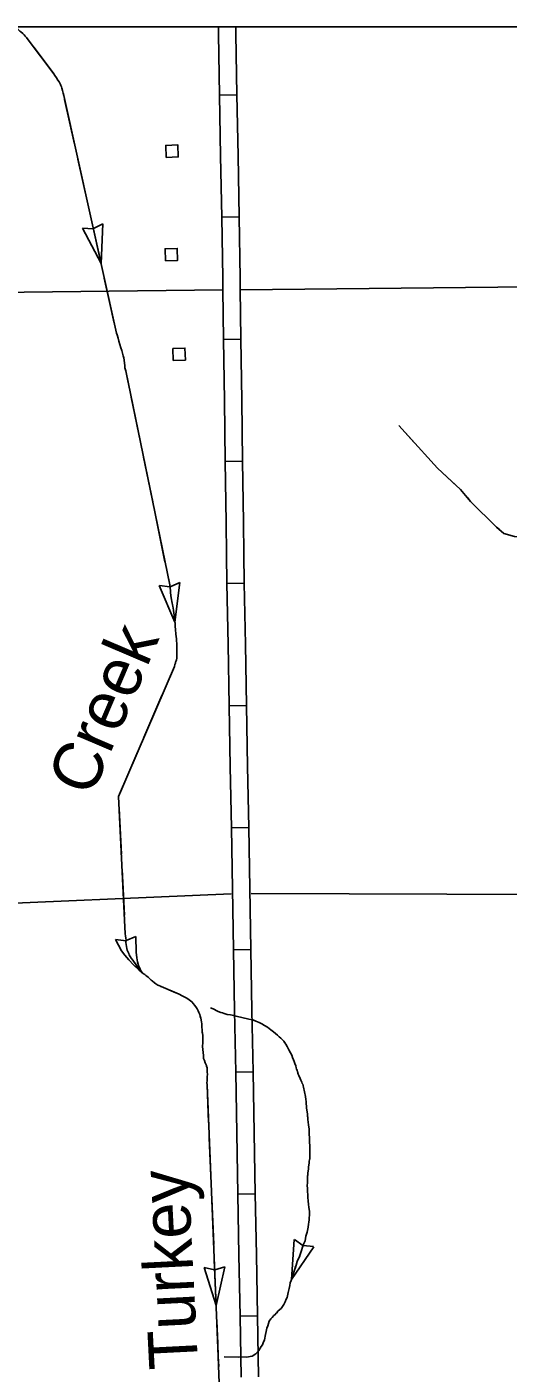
# Model space of a CAD drawing. Extents: x 1084508 to 1142749, y 1057638 to 1093403.
# Drawn here: x 1095928 to 1097232, y 1089750 to 1093403 of the extents above; entities that cross this region are included whole.
import ezdxf

# ---------------------------------------------------------------- set-up
doc = ezdxf.new("R2010")
doc.units = 0
for name, color, linetype in [('DSN_DRFT_Named-Boundary', 7, 'Continuous'), ('Level 31', 7, 'Continuous'), ('Level 35', 7, 'Continuous'), ('Level 43', 7, 'Continuous'), ('Level 5', 7, 'Continuous'), ('Level 56', 7, 'Continuous')]:
    doc.layers.add(name, color=color, linetype=linetype)

msp = doc.modelspace()

# ---------------------------------------------------------------- linework, layer by layer
at = {"layer": 'DSN_DRFT_Named-Boundary'}
msp.add_lwpolyline([(1084507.9, 1057640), (1142749.2, 1057640), (1142749.2, 1093403.4), (1084507.9, 1093403.4)], close=True, dxfattribs=at)
at = {"layer": 'Level 31'}
for p, q in [((1096447, 1093403.4), (1096447.3, 1093383.9)), ((1096494.1, 1093403.4), (1096494.4, 1093384.7)), ((1096497.2, 1093219), (1096450.1, 1093218.2)), ((1096455.7, 1092886.8), (1096502.8, 1092887.6)), ((1096460.8, 1092555.4), (1096507.9, 1092556.1)), ((1096512.3, 1092224.6), (1096465.2, 1092224)), ((1096470, 1091892.5), (1096517.1, 1091893.3)), ((1096523, 1091561.9), (1096475.9, 1091561.1)), ((1096481.9, 1091229.7), (1096528.9, 1091230.5)), ((1096534.9, 1090899.1), (1096487.8, 1090898.2)), ((1096540.8, 1090567.7), (1096493.7, 1090566.8)), ((1096499.6, 1090235.4), (1096546.7, 1090236.3)), ((1096505.6, 1089904), (1096552.6, 1089904.9))]:
    msp.add_line(p, q, dxfattribs=at)
for points in [[(1096447.3, 1093383.9), (1096450.1, 1093218.2)], [(1096494.4, 1093384.7), (1096497.2, 1093219)], [(1096450.1, 1093218.2), (1096452.9, 1093052.5)], [(1096500, 1093053.3), (1096497.2, 1093219)], [(1096452.9, 1093052.5), (1096455.7, 1092886.8)], [(1096502.8, 1092887.6), (1096500, 1093053.3)], [(1096455.7, 1092886.8), (1096458.5, 1092721.1)], [(1096502.8, 1092887.6), (1096505.6, 1092721.9)], [(1096458.5, 1092721.1), (1096459, 1092691.1), (1096460.8, 1092555.4)], [(1096505.6, 1092721.9), (1096506.1, 1092691.8), (1096507.9, 1092556.1)], [(1096463, 1092389.7), (1096460.8, 1092555.4)], [(1096507.9, 1092556.1), (1096510.1, 1092390.3)], [(1096465.2, 1092224), (1096463, 1092389.7)], [(1096510.1, 1092390.3), (1096512.3, 1092224.6)], [(1096465.2, 1092224), (1096467.4, 1092058.3)], [(1096512.3, 1092224.6), (1096514.5, 1092058.9)], [(1096467.4, 1092058.3), (1096468.6, 1091971.3), (1096470, 1091892.5)], [(1096514.5, 1092058.9), (1096515.7, 1091972), (1096517.1, 1091893.3)], [(1096473, 1091726.8), (1096470, 1091892.5)], [(1096517.1, 1091893.3), (1096520, 1091727.6)], [(1096475.9, 1091561.1), (1096473, 1091726.8)], [(1096520, 1091727.6), (1096523, 1091561.9)], [(1096475.9, 1091561.1), (1096478.9, 1091395.4)], [(1096523, 1091561.9), (1096526, 1091396.2)], [(1096478.9, 1091395.4), (1096481.9, 1091229.7)], [(1096526, 1091396.2), (1096528.9, 1091230.5)], [(1096484.8, 1091064), (1096481.9, 1091229.7)], [(1096528.9, 1091230.5), (1096531.9, 1091064.8)], [(1096487.8, 1090898.2), (1096484.8, 1091064)], [(1096531.9, 1091064.8), (1096534.9, 1090899.1)], [(1096487.8, 1090898.2), (1096490.7, 1090732.5)], [(1096534.9, 1090899.1), (1096537.8, 1090733.4)], [(1096490.7, 1090732.5), (1096493.7, 1090566.8)], [(1096537.8, 1090733.4), (1096540.8, 1090567.7)], [(1096493.7, 1090566.8), (1096496.7, 1090401.1)], [(1096543.7, 1090402), (1096540.8, 1090567.7)], [(1096496.7, 1090401.1), (1096499.6, 1090235.4)], [(1096546.7, 1090236.3), (1096543.7, 1090402)], [(1096499.6, 1090235.4), (1096502.6, 1090069.7)], [(1096546.7, 1090236.3), (1096549.7, 1090070.6)], [(1096502.6, 1090069.7), (1096505.6, 1089904)], [(1096549.7, 1090070.6), (1096552.6, 1089904.9)], [(1096508.5, 1089738.3), (1096505.6, 1089904)], [(1096552.6, 1089904.9), (1096555.6, 1089739.2)]]:
    msp.add_lwpolyline(points, dxfattribs=at)
at = {"layer": 'Level 43'}
for p, q in [((1096133.1, 1092869.1), (1096107.7, 1092855.9)), ((1096128.4, 1092761.5), (1096133.1, 1092869.1)), ((1096128.4, 1092761.5), (1096078.6, 1092857.1)), ((1096078.6, 1092857.1), (1096107.3, 1092855.8)), ((1096328.9, 1091788), (1096286.3, 1091887.3)), ((1096286.8, 1091887.4), (1096315.3, 1091883.9)), ((1096342, 1091895.1), (1096315.6, 1091883.9)), ((1096328.9, 1091788.2), (1096342.4, 1091895.3)), ((1096222.9, 1090934.6), (1096196.6, 1090923.4)), ((1096167.7, 1090926.7), (1096196.2, 1090923.3)), ((1096644.9, 1090004), (1096705.3, 1090092.7)), ((1096645.1, 1090004), (1096652.7, 1090112.1)), ((1096652.8, 1090112.3), (1096676.2, 1090095.7)), ((1096705.1, 1090092.9), (1096676.5, 1090095.6)), ((1096440.8, 1089933.2), (1096408.6, 1090036)), ((1096408.6, 1090036), (1096436.6, 1090029.7)), ((1096464.4, 1090038.3), (1096437, 1090029.7)), ((1096440.8, 1089933.2), (1096464.4, 1090038.3))]:
    msp.add_line(p, q, dxfattribs=at)
for points in [[(1095897.6, 1093403.4), (1095899.7, 1093401), (1095902.3, 1093398.3), (1095908.3, 1093392), (1095910.8, 1093390.1), (1095916, 1093385.8), (1095919.7, 1093381.6), (1095923, 1093378.2), (1095926.1, 1093374.7), (1095928.5, 1093371.8), (1096000.1, 1093275.6), (1096002.8, 1093271.3), (1096007.4, 1093265.2), (1096011.4, 1093259), (1096014.7, 1093254.7), (1096018.1, 1093247)], [(1095946.7, 1093347.4), (1096000.1, 1093275.6), (1096002.8, 1093271.3), (1096007.4, 1093265.2), (1096011.4, 1093259), (1096014.7, 1093254.7), (1096018.1, 1093247), (1096018.5, 1093246.2)], [(1096018.1, 1093247), (1096019.4, 1093244.4), (1096020.9, 1093241.1), (1096022.1, 1093236.8), (1096023.8, 1093231.1), (1096025.6, 1093223.9), (1096027.5, 1093216.8), (1096170.4, 1092572), (1096171.8, 1092567.6), (1096174.7, 1092558.9), (1096176.8, 1092550.8), (1096179.7, 1092541.5), (1096182.2, 1092532.8), (1096184.7, 1092524.7), (1096188.7, 1092510.9), (1096189.9, 1092505.3), (1096191.4, 1092499.1), (1096192.3, 1092490.9), (1096193.2, 1092484.7), (1096193.4, 1092478.4), (1096195.6, 1092470.3), (1096314.7, 1091888.8), (1096315.1, 1091886.2), (1096315.6, 1091881.6), (1096316.6, 1091872.3), (1096317.1, 1091868.6), (1096318, 1091860.1), (1096319, 1091854.2), (1096321.5, 1091839.4), (1096322.4, 1091836.2), (1096323.2, 1091829.9), (1096324, 1091826.5), (1096324.9, 1091819.3), (1096325.7, 1091813), (1096326.6, 1091806.8), (1096327, 1091802.1), (1096328.4, 1091791.1), (1096329.2, 1091783.6), (1096329.9, 1091777.3), (1096329.9, 1091774.8), (1096330.2, 1091769.1), (1096330.7, 1091764.1), (1096331.1, 1091759.2), (1096331.3, 1091755.3), (1096332.2, 1091749), (1096332.7, 1091743.4), (1096333.3, 1091738.3), (1096333.5, 1091735.5), (1096333.8, 1091731.8), (1096334.3, 1091725.8), (1096334.4, 1091722.1), (1096334.3, 1091717), (1096334.2, 1091712.3), (1096334.2, 1091709.2), (1096334.1, 1091706.9), (1096333.9, 1091703.1), (1096333.8, 1091700.1), (1096333.8, 1091696.8), (1096334, 1091693), (1096333.7, 1091690.5), (1096333, 1091686), (1096331.8, 1091682.9), (1096330.7, 1091679), (1096330.2, 1091676.5), (1096329, 1091672.7), (1096327.3, 1091667.6), (1096176.1, 1091314.2), (1096194.3, 1090941.9), (1096195.1, 1090936.3), (1096195.3, 1090930.6), (1096196.2, 1090924.6), (1096196, 1090918.2), (1096196.7, 1090913.1), (1096197.5, 1090907.4), (1096198.6, 1090901.7), (1096199.7, 1090897.7), (1096201.1, 1090893.7), (1096203.5, 1090888.4), (1096205.2, 1090885), (1096210.4, 1090876.2), (1096214.6, 1090870.8), (1096218.5, 1090865.2), (1096222.1, 1090860.3), (1096225.9, 1090854.3), (1096231.8, 1090846.3), (1096237.1, 1090840.2), (1096240.9, 1090835.3), (1096246.9, 1090831.1), (1096250.1, 1090828.7), (1096252.7, 1090826.6), (1096256, 1090823.9), (1096259.9, 1090820.9), (1096264.4, 1090816.6), (1096267, 1090814.2), (1096273.5, 1090808.8), (1096277.4, 1090806.4), (1096282.6, 1090802.8), (1096287.7, 1090800.5), (1096290.3, 1090799.3), (1096291.5, 1090798.8), (1096340.1, 1090778.5)], [(1096029.8, 1093206.5), (1096056.7, 1093085.1)], [(1096065.6, 1093044.7), (1096092.5, 1092923.3)], [(1096101.5, 1092882.9), (1096128.4, 1092761.5)], [(1096137.3, 1092721.1), (1096150.8, 1092660.4)], [(1096150.8, 1092660.4), (1096164.2, 1092599.7)], [(1096174.4, 1092559.6), (1096174.7, 1092558.9), (1096176.8, 1092550.8), (1096179.7, 1092541.5), (1096182.2, 1092532.8), (1096184.7, 1092524.7), (1096188.7, 1092510.9), (1096189.9, 1092505.3), (1096191.4, 1092499.1), (1096192.3, 1092490.9), (1096193.2, 1092484.7), (1096193.4, 1092478.4), (1096195.6, 1092470.3), (1096202, 1092438.7)], [(1096210.4, 1092398.1), (1096235.3, 1092276.4)], [(1096935.9, 1092321.6), (1097040.8, 1092205.7), (1097103.3, 1092148), (1097130.8, 1092115.4), (1097201.4, 1092046), (1097221.3, 1092028.4), (1097249.4, 1092019.9), (1097401.5, 1092007.1), (1097402.4, 1091992), (1097402.7, 1091952.6), (1097403.5, 1091917.6), (1097419.3, 1091871), (1097436.4, 1091831.9), (1097460.2, 1091765.7), (1097473, 1091720.9), (1097516.4, 1091515.8), (1097525.3, 1091489.6)], [(1096935.9, 1092321.6), (1096977.6, 1092275.5)], [(1096243.6, 1092235.8), (1096268.6, 1092114)], [(1097005.4, 1092244.8), (1097040.8, 1092205.7), (1097093.4, 1092157.2)], [(1097121.3, 1092126.7), (1097130.8, 1092115.4), (1097201.4, 1092046), (1097209.3, 1092039)], [(1096276.9, 1092073.4), (1096301.9, 1091951.7)], [(1096310.2, 1091911.1), (1096314.7, 1091888.8), (1096315.1, 1091886.2), (1096315.6, 1091881.6), (1096316.6, 1091872.3), (1096317.1, 1091868.6), (1096318, 1091860.1), (1096319, 1091854.2), (1096321.5, 1091839.4), (1096322.4, 1091836.2), (1096323.2, 1091829.9), (1096324, 1091826.5), (1096324.9, 1091819.3), (1096325.7, 1091813), (1096326.6, 1091806.8), (1096327, 1091802.1), (1096328.4, 1091791.1), (1096328.7, 1091788.3)], [(1096332.4, 1091747), (1096332.7, 1091743.4), (1096333.3, 1091738.3), (1096333.5, 1091735.5), (1096333.8, 1091731.8), (1096334.3, 1091725.8), (1096334.4, 1091722.1), (1096334.3, 1091717), (1096334.2, 1091712.3), (1096334.2, 1091709.2), (1096334.1, 1091706.9), (1096333.9, 1091703.1), (1096333.8, 1091700.1), (1096333.8, 1091696.8), (1096334, 1091693), (1096333.7, 1091690.5), (1096333, 1091686), (1096332.6, 1091685.1)], [(1096332.6, 1091685.1), (1096331.8, 1091682.9), (1096330.7, 1091679), (1096330.2, 1091676.5), (1096329, 1091672.7), (1096327.3, 1091667.6), (1096310.1, 1091627.3)], [(1096293.8, 1091589.2), (1096244.9, 1091474.9)], [(1096228.6, 1091436.8), (1096179.7, 1091322.6)], [(1096177.7, 1091281.9), (1096183.7, 1091157.8)], [(1096185.8, 1091116.4), (1096191.8, 1090992.2)], [(1096193.8, 1090950.8), (1096194.3, 1090941.9), (1096195.1, 1090936.3), (1096195.3, 1090930.6), (1096196.2, 1090924.6), (1096196, 1090918.2), (1096196.7, 1090913.1), (1096197.5, 1090907.4), (1096198.6, 1090901.7), (1096199.7, 1090897.7), (1096201.1, 1090893.7), (1096203.5, 1090888.4), (1096205.2, 1090885), (1096210.4, 1090876.2), (1096214.6, 1090870.8), (1096218.5, 1090865.2), (1096222.1, 1090860.3), (1096225.9, 1090854.3), (1096231.8, 1090846.3), (1096237.1, 1090840.2), (1096238.1, 1090838.9)], [(1096223.1, 1090934.6), (1096223.5, 1090892.1), (1096225.6, 1090877.1), (1096227.8, 1090865.6), (1096230.5, 1090855.9), (1096235, 1090845.6), (1096238.6, 1090838.7)], [(1096167.3, 1090926.7), (1096184.1, 1090896), (1096193.2, 1090883.6), (1096203.7, 1090871.4), (1096216.6, 1090857.8), (1096230.9, 1090843.8), (1096238.4, 1090838.2)], [(1096269.6, 1090812.1), (1096273.5, 1090808.8), (1096277.4, 1090806.4), (1096282.6, 1090802.8), (1096287.7, 1090800.5), (1096290.3, 1090799.3), (1096291.5, 1090798.8), (1096325.1, 1090784.8)], [(1096325.1, 1090784.8), (1096340.1, 1090778.5), (1096348.5, 1090773.8), (1096354.1, 1090770.7), (1096357.1, 1090769), (1096359.3, 1090767.9), (1096363.9, 1090765.2), (1096367.8, 1090762.6), (1096374.6, 1090757.1), (1096378, 1090753.3)], [(1096340.1, 1090778.5), (1096348.5, 1090773.8), (1096354.1, 1090770.7), (1096357.1, 1090769), (1096359.3, 1090767.9), (1096363.9, 1090765.2), (1096367.8, 1090762.6), (1096374.6, 1090757.1), (1096378.9, 1090752.3), (1096382.1, 1090748.2), (1096385.3, 1090743.9), (1096388.9, 1090738.1), (1096392.2, 1090732.6), (1096394.1, 1090728.2), (1096396.1, 1090722.8), (1096397.2, 1090718.6), (1096398.8, 1090712.8), (1096400.9, 1090703.3), (1096401.7, 1090697.7), (1096401.9, 1090693.9), (1096402.1, 1090687.6), (1096402.3, 1090682.6), (1096402.4, 1090678.8), (1096402.9, 1090675.4), (1096403.3, 1090672.5), (1096404.2, 1090665.6), (1096404.5, 1090655.6), (1096404.2, 1090647.4), (1096404, 1090636), (1096406.2, 1090611.5), (1096406.3, 1090607.8), (1096406.5, 1090603.4), (1096407.3, 1090601.6), (1096407.8, 1090600.3), (1096409.2, 1090597.8), (1096411.3, 1090592.2), (1096412, 1090590.3), (1096414.4, 1090584.6), (1096414.8, 1090582.9), (1096416.2, 1090577.9), (1096416.4, 1090573.5), (1096416.5, 1090570.3), (1096416.7, 1090565.3), (1096416.8, 1090561.5), (1096416.5, 1090552.7), (1096416.1, 1090547.7), (1096415.9, 1090542.1), (1096415.8, 1090538.8), (1096416, 1090532.5), (1096446.5, 1089794.7), (1096468.9, 1089190.8)], [(1096397.5, 1090717.2), (1096398.8, 1090712.8), (1096400.9, 1090703.3), (1096401.7, 1090697.7), (1096401.9, 1090693.9), (1096402.1, 1090687.6), (1096402.3, 1090682.6), (1096402.4, 1090678.8), (1096402.9, 1090675.4), (1096403.3, 1090672.5), (1096404.2, 1090665.6), (1096404.5, 1090655.6), (1096404.2, 1090647.4), (1096404, 1090636), (1096406.2, 1090611.5), (1096406.3, 1090607.8), (1096406.5, 1090603.4), (1096407.3, 1090601.6), (1096407.8, 1090600.3), (1096409.2, 1090597.8), (1096410.4, 1090594.5)], [(1096425.2, 1090741.1), (1096432.3, 1090738.3), (1096436.1, 1090736.5), (1096441.1, 1090733.7), (1096446.4, 1090731.3), (1096453.5, 1090728.4), (1096457.9, 1090727.3), (1096462.4, 1090725.6), (1096470.7, 1090723.4), (1096479.9, 1090721.9), (1096487.8, 1090720.3), (1096494.6, 1090718.1), (1096529.2, 1090710.7), (1096539.4, 1090708.5), (1096548.4, 1090704.5), (1096557.3, 1090701.1), (1096564.4, 1090697.6), (1096571.5, 1090693.4), (1096579.9, 1090688.7), (1096589.3, 1090681.6), (1096596.2, 1090675.5), (1096602, 1090671.3), (1096606.9, 1090666.5), (1096611.8, 1090662.6), (1096616.4, 1090658.4), (1096620.4, 1090653.8), (1096624.3, 1090650.2), (1096627, 1090646.5), (1096629.7, 1090642.2), (1096633.1, 1090636), (1096637.9, 1090626.8), (1096642, 1090618.7), (1096646, 1090612.3), (1096647.5, 1090606.3), (1096650.3, 1090600.1), (1096652.4, 1090595.2), (1096654.5, 1090589.6), (1096656.6, 1090584), (1096658.1, 1090578.4), (1096658.9, 1090574.6), (1096660.3, 1090571.5), (1096661.1, 1090567.2), (1096661.8, 1090565.3), (1096662.5, 1090563.4), (1096663.2, 1090560.9), (1096664.6, 1090557.8), (1096666, 1090554.7), (1096667.4, 1090551.6), (1096668.8, 1090549.2), (1096670.2, 1090544.8), (1096672.9, 1090539.3), (1096674.3, 1090535.8), (1096675.7, 1090533.7), (1096676.4, 1090530.6), (1096677.1, 1090529), (1096677.9, 1090525.6), (1096682.7, 1090500.5), (1096684.6, 1090485.5), (1096685.9, 1090469.1), (1096688.4, 1090453.5), (1096689.7, 1090438.4), (1096690.9, 1090423.3), (1096692.6, 1090412), (1096693.3, 1090396.9), (1096693.6, 1090388.7), (1096694, 1090379.3), (1096694.6, 1090364.2), (1096695, 1090353.5), (1096694.7, 1090345.9), (1096694.3, 1090340.2), (1096694.3, 1090332), (1096693, 1090325), (1096692.6, 1090320.6), (1096691.6, 1090313.6), (1096691.2, 1090309.2), (1096690.8, 1090303.5), (1096690.3, 1090298.7), (1096689.3, 1090292.7), (1096688.9, 1090288.6), (1096688.2, 1090281.9), (1096688.6, 1090278.8), (1096688.2, 1090274.4), (1096688.4, 1090269.3), (1096688, 1090264.3), (1096687.5, 1090260.8), (1096688, 1090248.5), (1096688.9, 1090227.1), (1096690.2, 1090216.4), (1096691.5, 1090208.3), (1096691.9, 1090198.9), (1096693.5, 1090189.5), (1096694.1, 1090184.4), (1096693.4, 1090178.7), (1096693, 1090171.2), (1096692.6, 1090165.5), (1096692.3, 1090159.1), (1096691.2, 1090154.1), (1096690.3, 1090146.1), (1096687.1, 1090132.4), (1096684.3, 1090121.6), (1096681.7, 1090108.9)], [(1096425.2, 1090741.1), (1096432.3, 1090738.3), (1096436.1, 1090736.5), (1096441.1, 1090733.7), (1096446.4, 1090731.3), (1096453.5, 1090728.4), (1096457.9, 1090727.3), (1096462.4, 1090725.6), (1096470.7, 1090723.4), (1096479.9, 1090721.9), (1096483.7, 1090721.2)], [(1096538.3, 1090709), (1096548.4, 1090704.5), (1096557.3, 1090701.1), (1096564.4, 1090697.6), (1096571.5, 1090693.4), (1096579.9, 1090688.7), (1096589.3, 1090681.6), (1096596.2, 1090675.5), (1096602, 1090671.3), (1096606.9, 1090666.5), (1096611.8, 1090662.6), (1096616.4, 1090658.4), (1096620.4, 1090653.8), (1096624.3, 1090650.2), (1096626.9, 1090646.6)], [(1096646.5, 1090610.2), (1096647.5, 1090606.3), (1096650.3, 1090600.1), (1096652.4, 1090595.2), (1096654.5, 1090589.6), (1096656.6, 1090584), (1096658.1, 1090578.4), (1096658.9, 1090574.6), (1096660.3, 1090571.5), (1096661.1, 1090567.2), (1096661.8, 1090565.3), (1096662.5, 1090563.4), (1096663.2, 1090560.9), (1096664.6, 1090557.8), (1096666, 1090554.7), (1096667.4, 1090551.6), (1096668.8, 1090549.2), (1096670.2, 1090544.8), (1096672.9, 1090539.3), (1096674.3, 1090535.8), (1096675.7, 1090533.7), (1096676.4, 1090530.6), (1096677.1, 1090529), (1096677.9, 1090525.6), (1096682.7, 1090500.5), (1096683.7, 1090492.4)], [(1096416.6, 1090554.1), (1096416.5, 1090552.7), (1096416.1, 1090547.7), (1096415.9, 1090542.1), (1096415.8, 1090538.8), (1096416, 1090532.5), (1096420.3, 1090429.9)], [(1096688.6, 1090451.3), (1096689.7, 1090438.4), (1096690.9, 1090423.3), (1096692.6, 1090412), (1096693.3, 1090396.9), (1096693.6, 1090388.7), (1096694, 1090379.3), (1096694.6, 1090364.2), (1096695, 1090353.5), (1096694.7, 1090345.9), (1096694.3, 1090340.2), (1096694.3, 1090332), (1096693.5, 1090327.4)], [(1096422, 1090388.5), (1096427.1, 1090264.3)], [(1096688.6, 1090286.3), (1096688.2, 1090281.9), (1096688.6, 1090278.8), (1096688.2, 1090274.4), (1096688.4, 1090269.3), (1096688, 1090264.3), (1096687.5, 1090260.8), (1096688, 1090248.5), (1096688.9, 1090227.1), (1096690.2, 1090216.4), (1096691.5, 1090208.3), (1096691.9, 1090198.9), (1096693.5, 1090189.5), (1096694.1, 1090184.4), (1096693.4, 1090178.7), (1096693, 1090171.2), (1096692.6, 1090165.5), (1096692.5, 1090162.6)], [(1096428.8, 1090222.9), (1096434, 1090098.7)], [(1096681.7, 1090108.9), (1096677.7, 1090099.3), (1096674.9, 1090091.6), (1096672.1, 1090082), (1096669.3, 1090074.3), (1096666.5, 1090065.4), (1096664.1, 1090060.9), (1096660.7, 1090052.6), (1096657.3, 1090042.6), (1096655.1, 1090036.6), (1096652.9, 1090028.9), (1096650, 1090020.6), (1096647.8, 1090014.8), (1096645.6, 1090005.9), (1096643.9, 1090000.8), (1096641.6, 1089995), (1096640.1, 1089987.4), (1096638.5, 1089979.1), (1096636.4, 1089968.6), (1096633.2, 1089955), (1096630.9, 1089950.4), (1096627.4, 1089943.4), (1096623.9, 1089935.7), (1096621, 1089930.2), (1096616.8, 1089925.3), (1096613.1, 1089922), (1096608.3, 1089917.4), (1096604.8, 1089913.4), (1096600.4, 1089908.9), (1096596.8, 1089905.6), (1096592.3, 1089901), (1096588.9, 1089897), (1096584.8, 1089890.6), (1096580.6, 1089878.4), (1096578, 1089871.4), (1096576.2, 1089862.8), (1096574.9, 1089854.2), (1096571.8, 1089839.6), (1096568.3, 1089831.9), (1096566, 1089826.7), (1096563.1, 1089821.5), (1096560.2, 1089817.8), (1096556.9, 1089812), (1096551.5, 1089805.8), (1096548.6, 1089802.4), (1096546.2, 1089800.7), (1096542.6, 1089798.1), (1096538.3, 1089796), (1096532.6, 1089794.5), (1096528.3, 1089793.7), (1096522.6, 1089792.8), (1096462.1, 1089793.5)], [(1096684.4, 1090122), (1096684.3, 1090121.6), (1096681.7, 1090108.9), (1096677.7, 1090099.3), (1096674.9, 1090091.6), (1096672.1, 1090082), (1096669.3, 1090074.3), (1096666.5, 1090066.5), (1096664.1, 1090060.9), (1096660.7, 1090052.6), (1096657.3, 1090042.6), (1096655.5, 1090036.3), (1096652.9, 1090028.9), (1096650, 1090020.6), (1096648.3, 1090014.4), (1096645.6, 1090005.9), (1096645.1, 1090004.4)], [(1096435.7, 1090057.3), (1096440.8, 1089933.2)], [(1096635.4, 1089964.2), (1096633.2, 1089955), (1096630.9, 1089950.4), (1096627.4, 1089943.4), (1096623.9, 1089935.7), (1096621, 1089930.2), (1096616.8, 1089925.3), (1096613.1, 1089922), (1096608.3, 1089917.4), (1096604.8, 1089913.4), (1096603.6, 1089912.2)], [(1096603.6, 1089912.2), (1096600.4, 1089908.9), (1096596.8, 1089905.6), (1096592.3, 1089901), (1096588.9, 1089897), (1096584.8, 1089890.6), (1096580.6, 1089878.4), (1096578, 1089871.4), (1096576.2, 1089862.8), (1096575.6, 1089858.6)], [(1096442.5, 1089891.8), (1096445.1, 1089829.7)], [(1096445.1, 1089829.7), (1096446.5, 1089794.7), (1096447.5, 1089767.6)], [(1096500.4, 1089793.1), (1096462.1, 1089793.5)]]:
    msp.add_lwpolyline(points, dxfattribs=at)
at = {"layer": 'Level 5'}
for points in [[(1095687.7, 1092681.2), (1096459.1, 1092689.4)], [(1096506.5, 1092689.9), (1097291.6, 1092698.2)], [(1096481.2, 1091050.7), (1095725.5, 1091017.6)], [(1096535.7, 1091051.7), (1097332, 1091048.9), (1098038.3, 1091054.1)]]:
    msp.add_lwpolyline(points, dxfattribs=at)
at = {"layer": 'Level 56'}
for points in [[(1096305.4, 1093049.1), (1096304.1, 1093081.8), (1096336.8, 1093083.1), (1096338.1, 1093050.5)], [(1096303.6, 1092768.5), (1096302.2, 1092801.1), (1096335, 1092802.4), (1096336.3, 1092769.8)], [(1096324.5, 1092497.7), (1096323.2, 1092530.4), (1096355.9, 1092531.7), (1096357.3, 1092499)]]:
    msp.add_lwpolyline(points, close=True, dxfattribs=at)

# ---------------------------------------------------------------- texts
at = {"layer": 'Level 35'}
for s, rotation, p in [('Creek', 66.8775, (1096101.8, 1091309.5)), ('Turkey', 92.8898, (1096392, 1089763))]:
    msp.add_text(s, height=132.58, rotation=rotation, dxfattribs=at).set_placement(p)

doc.saveas('drawing.dxf')
